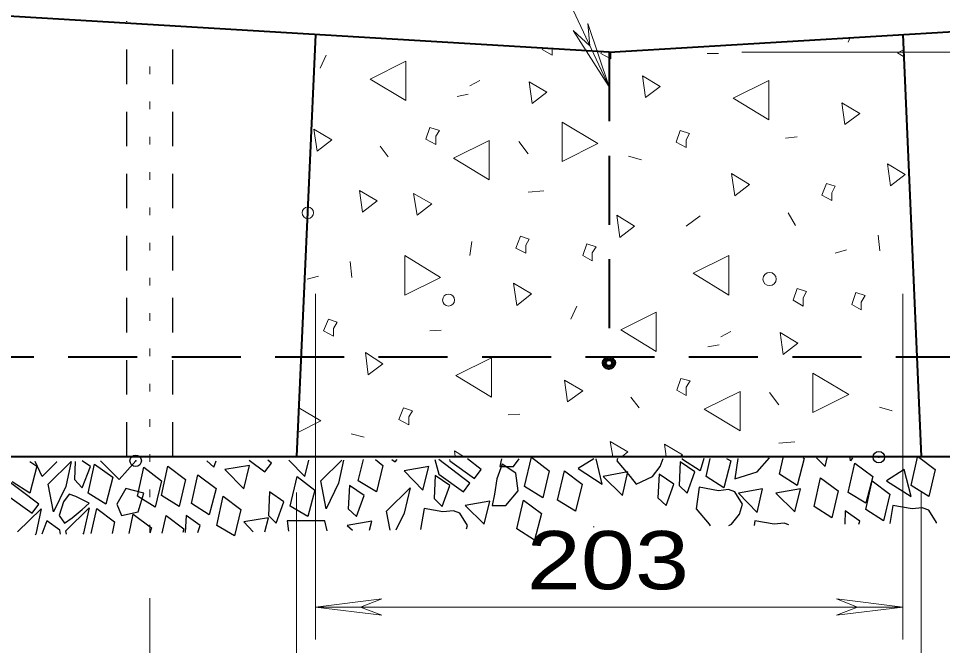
# Model space of a CAD drawing. Extents: x 312583 to 312854, y 144419 to 144597.
# Drawn here: x 312703.67 to 312715.73, y 144449.15 to 144457.33 of the extents above; entities that cross this region are included whole.
import ezdxf

# ---------------------------------------------------------------- set-up
doc = ezdxf.new("R2010")
doc.units = 0
doc.header["$LTSCALE"] = 0.3
doc.header["$PDMODE"] = 32
doc.header["$PDSIZE"] = 0.15
for name, pattern in [('DOTTED', [1.5, 0.3, -1.2]), ('MEDIUM_DASHED', [4.5, 3, -1.5]), ('SHORT_DASHED', [2.7, 1.5, -1.2])]:
    doc.linetypes.add(name, pattern=pattern)
doc.layers.add('1', color=7, linetype='Continuous', lineweight=25)
doc.layers.add('2', color=7, linetype='Continuous', lineweight=13)

msp = doc.modelspace()

# ---------------------------------------------------------------- linework, layer by layer
at = {"layer": '1', "lineweight": 40}
for p, q in [((312711.376, 144456.89), (312703.464, 144457.3654)), ((312711.376, 144456.89), (312719.2804, 144457.3654)), ((312707.5427, 144457.12), (312707.2974, 144451.6154)), ((312715.2094, 144457.12), (312715.447, 144451.6154)), ((312697.001, 144451.6154), (312725.751, 144451.6154))]:
    msp.add_line(p, q, dxfattribs=at)
at = {"layer": '1', "linetype": 'SHORT_DASHED'}
for p, q in [((312705.0817, 144451.6154), (312705.0817, 144457.2964)), ((312705.6797, 144451.6154), (312705.6797, 144457.258))]:
    msp.add_line(p, q, dxfattribs=at)
at = {"layer": '1', "linetype": 'MEDIUM_DASHED', "lineweight": 40}
for p, q in [((312711.376, 144456.89), (312711.376, 144452.9187)), ((312698.9177, 144452.9187), (312723.8344, 144452.9187))]:
    msp.add_line(p, q, dxfattribs=at)
at = {"layer": '1'}
for p, q in [((312708.1024, 144451.301), (312708.1714, 144451.577)), ((312709.099, 144451.577), (312709.1527, 144451.3854)), ((312709.2907, 144451.577), (312709.2984, 144451.5617)), ((312711.1767, 144451.5847), (312710.9697, 144451.462)), ((312712.3344, 144451.577), (312712.3344, 144451.5924)), ((312712.641, 144451.3547), (312712.6947, 144451.5924)), ((312713.5994, 144451.3854), (312713.6454, 144451.6)), ((312715.3167, 144451.2397), (312715.401, 144451.6077)), ((312703.9777, 144451.3547), (312703.8857, 144451.554)), ((312707.6117, 144451.301), (312707.8877, 144451.5694)), ((312708.5164, 144450.657), (312708.4704, 144450.9024)), ((312714.458, 144450.91), (312714.4504, 144450.7337)), ((312704.039, 144450.7797), (312703.97, 144450.6034)), ((312705.856, 144450.8487), (312705.8407, 144450.6264)), ((312706.6074, 144450.7644), (312706.73, 144450.634)), ((312712.6794, 144450.7337), (312712.6947, 144450.7107)), ((312704.292, 144450.6034), (312704.2844, 144450.6494)), ((312707.9567, 144450.7184), (312708.0257, 144450.657)), ((312711.1767, 144450.6954), (312711.1767, 144450.703))]:
    msp.add_line(p, q, dxfattribs=at)
for points in [[(312708.3247, 144451.577), (312708.4244, 144451.5004), (312708.34, 144451.1554), (312708.1024, 144451.301)], [(312708.5394, 144451.577), (312708.5854, 144451.5464), (312708.6084, 144451.577)], [(312709.1527, 144451.3854), (312709.4747, 144451.1554), (312709.559, 144451.2704), (312709.1527, 144451.577)], [(312709.2984, 144451.5617), (312709.6204, 144451.3317), (312709.7047, 144451.4467), (312709.5284, 144451.5847)], [(312709.973, 144451.5847), (312709.95, 144451.485), (312710.1264, 144451.485), (312710.203, 144451.5847)], [(312710.9697, 144451.462), (312711.284, 144451.255), (312711.2074, 144451.5847)], [(312711.4834, 144451.5924), (312711.4757, 144451.5617), (312711.652, 144451.3547)], [(312711.652, 144451.3547), (312711.7287, 144451.255), (312711.9434, 144451.3547), (312712.043, 144451.485), (312712.0814, 144451.5924)], [(312712.6104, 144451.5924), (312712.5644, 144451.4314), (312712.3344, 144451.577)], [(312712.9094, 144451.5924), (312712.963, 144451.5617), (312712.871, 144451.209), (312712.641, 144451.3547)], [(312713.055, 144451.5924), (312713.0167, 144451.324), (312713.308, 144451.416), (312713.469, 144451.6)], [(312713.906, 144451.6), (312713.9214, 144451.5924), (312713.8294, 144451.2397), (312713.5994, 144451.3854)], [(312714.0824, 144451.6), (312714.1974, 144451.485), (312714.2204, 144451.6)], [(312714.55, 144451.6), (312714.527, 144451.5617), (312714.5194, 144451.6)], [(312715.4164, 144451.6077), (312715.631, 144451.4467), (312715.5467, 144451.094), (312715.3167, 144451.2397)], [(312703.8167, 144451.554), (312703.9087, 144451.4927), (312703.8167, 144451.14), (312703.5867, 144451.2857)], [(312704.1617, 144451.554), (312704.1694, 144451.5464), (312703.9777, 144451.3547)], [(312704.407, 144451.554), (312704.3994, 144451.3164), (312704.499, 144451.209), (312704.6064, 144451.485), (312704.499, 144451.5617)], [(312704.7367, 144451.5617), (312704.982, 144451.3164), (312705.1967, 144451.5617)], [(312706.1244, 144451.5617), (312706.2164, 144451.4774), (312706.247, 144451.5617)], [(312706.6764, 144451.5694), (312706.8834, 144451.416), (312706.9677, 144451.531), (312706.9217, 144451.5694)], [(312707.1977, 144451.5694), (312707.4047, 144451.3547), (312707.4584, 144451.5694)], [(312707.9107, 144451.5694), (312707.8417, 144451.2704), (312707.6807, 144450.933), (312707.6117, 144451.301)], [(312712.94, 144450.7184), (312712.9707, 144450.7337), (312713.078, 144450.864), (312713.1164, 144450.9944), (312713.0167, 144451.1554), (312712.9324, 144451.186), (312712.802, 144451.1707), (312712.549, 144451.2167), (312712.5107, 144450.933), (312712.6794, 144450.7337)], [(312708.4704, 144450.9024), (312708.777, 144451.209), (312708.7004, 144450.8794), (312708.593, 144450.657)], [(312715.6464, 144450.749), (312715.6464, 144450.7567), (312715.5467, 144450.9177), (312715.4624, 144450.9484), (312715.332, 144450.933), (312715.079, 144450.979), (312715.0407, 144450.7414)], [(312703.6557, 144450.634), (312703.9624, 144450.933), (312703.8934, 144450.6034), (312703.8857, 144450.5957)], [(312704.2844, 144450.6494), (312704.591, 144450.9484), (312704.5144, 144450.6187), (312704.5067, 144450.6034)], [(312704.614, 144450.611), (312704.6907, 144450.9407), (312704.9207, 144450.7644), (312704.89, 144450.611)], [(312705.1124, 144450.611), (312705.166, 144450.864), (312705.4037, 144450.6877), (312705.3807, 144450.6187)], [(312709.513, 144450.6724), (312709.5284, 144450.7184), (312709.4287, 144450.8794), (312709.3444, 144450.91), (312709.2064, 144450.8947), (312708.961, 144450.9407), (312708.915, 144450.6647)], [(312714.6344, 144450.7337), (312714.6497, 144450.772), (312714.458, 144450.91)], [(312704.2154, 144450.6034), (312704.2077, 144450.657), (312704.039, 144450.7797)], [(312705.5417, 144450.6187), (312705.5954, 144450.8487), (312705.8254, 144450.6724), (312705.81, 144450.6264)], [(312706.0094, 144450.6264), (312706.04, 144450.7184), (312705.856, 144450.8487)], [(312706.8834, 144450.634), (312706.9294, 144450.818), (312706.6074, 144450.7644)], [(312707.696, 144450.6494), (312707.6654, 144450.7797), (312707.1747, 144450.7797), (312707.19, 144450.6417)], [(312708.248, 144450.657), (312708.2787, 144450.772), (312707.9567, 144450.7184)], [(312713.722, 144450.726), (312713.6607, 144450.749), (312713.5304, 144450.7337), (312713.2774, 144450.7797), (312713.2697, 144450.7184)]]:
    msp.add_lwpolyline(points, dxfattribs=at)
for points in [[(312710.272, 144451.2244), (312710.364, 144451.6077), (312710.594, 144451.4314), (312710.5097, 144451.0787)], [(312704.0544, 144451.255), (312704.3534, 144451.554), (312704.2844, 144451.2244), (312704.1234, 144450.8947)], [(312704.5757, 144451.14), (312704.66, 144451.5157), (312704.8977, 144451.347), (312704.8057, 144450.9944)], [(312705.2197, 144451.1017), (312705.304, 144451.4774), (312705.534, 144451.301), (312705.4497, 144450.956)], [(312705.534, 144451.1094), (312705.6184, 144451.4927), (312705.8484, 144451.3164), (312705.764, 144450.9637)], [(312706.362, 144451.4467), (312706.6074, 144451.1937), (312706.684, 144451.5004)], [(312708.7004, 144451.4314), (312708.9457, 144451.1784), (312709.0224, 144451.485)], [(312709.9807, 144451.5157), (312709.9117, 144451.324), (312709.881, 144451.1247), (312709.8504, 144450.979), (312710.0267, 144450.979), (312710.1877, 144451.1707), (312710.157, 144451.4007)], [(312712.3037, 144451.5464), (312712.2884, 144451.2397), (312712.3957, 144451.14), (312712.4954, 144451.416)], [(312714.4964, 144451.1477), (312714.5807, 144451.531), (312714.8184, 144451.3547), (312714.7264, 144451.0097)], [(312703.5254, 144451.1094), (312703.8474, 144450.8794), (312703.9317, 144450.9944), (312703.4564, 144451.3547)], [(312705.925, 144451.002), (312706.0094, 144451.3777), (312706.247, 144451.2014), (312706.155, 144450.8564)], [(312707.213, 144450.9714), (312707.305, 144451.3547), (312707.535, 144451.1784), (312707.443, 144450.8334)], [(312709.1067, 144451.37), (312709.0914, 144451.071), (312709.1987, 144450.9637), (312709.2984, 144451.2397)], [(312710.7014, 144451.048), (312710.7934, 144451.4314), (312711.0234, 144451.255), (312710.939, 144450.9024)], [(312711.2994, 144451.3547), (312711.5524, 144451.1094), (312711.6214, 144451.416)], [(312712.0277, 144451.3854), (312712.0124, 144451.0787), (312712.1197, 144450.979), (312712.2194, 144451.255)], [(312714.0517, 144450.9637), (312714.136, 144451.3394), (312714.366, 144451.1707), (312714.2817, 144450.818)], [(312714.9947, 144451.301), (312715.3167, 144451.094), (312715.2247, 144451.4467)], [(312707.9874, 144451.2397), (312707.972, 144450.933), (312708.0794, 144450.8334), (312708.179, 144451.1094)], [(312714.7264, 144450.9254), (312714.8107, 144451.301), (312715.0407, 144451.1247), (312714.9564, 144450.7797)], [(312704.4147, 144451.094), (312704.3304, 144451.1247), (312704.2537, 144451.025), (312704.2, 144450.8487), (312704.269, 144450.749), (312704.3687, 144450.818), (312704.499, 144450.9254), (312704.591, 144451.0097)], [(312705.0664, 144451.2014), (312704.9514, 144450.9944), (312705.0127, 144450.8487), (312705.2274, 144450.8947), (312705.304, 144451.14)], [(312706.2547, 144450.7184), (312706.339, 144451.1017), (312706.569, 144450.9254), (312706.4847, 144450.5804)], [(312706.9447, 144451.1554), (312706.9294, 144450.8487), (312707.029, 144450.749), (312707.1287, 144451.025)], [(312713.0627, 144451.14), (312713.308, 144450.887), (312713.377, 144451.1937)], [(312713.5534, 144451.14), (312713.7987, 144450.8947), (312713.8754, 144451.1937)], [(312709.4977, 144450.979), (312709.743, 144450.7337), (312709.8197, 144451.0327)], [(312710.1724, 144450.6724), (312710.2567, 144451.048), (312710.4944, 144450.8717), (312710.4024, 144450.5267)]]:
    msp.add_lwpolyline(points, close=True, dxfattribs=at)
at = {"layer": '1', "lineweight": 40}
for radius in [0.0799, 0.0559, 0.0391]:
    msp.add_circle((312711.3732, 144452.8369), radius, dxfattribs=at)
at = {"layer": '1'}
for p in [(312705.1967, 144451.5617), (312714.895, 144451.6077)]:
    msp.add_point(p, dxfattribs=at)
at = {"layer": '2'}
for p, q in [((312711.1, 144457.2657), (312711.123, 144456.9744)), ((312711.376, 144456.4377), (312711.1, 144457.2657)), ((312710.9084, 144457.1737), (312711.123, 144456.9744)), ((312711.376, 144456.4377), (312710.9084, 144457.1737)), ((312714.5194, 144457.0817), (312714.4964, 144457.0204)), ((312713.1087, 144456.89), (312728.9864, 144456.89)), ((312707.6807, 144456.8517), (312707.604, 144456.683)), ((312712.6564, 144456.8747), (312712.802, 144456.8747)), ((312709.559, 144456.453), (312709.6894, 144456.522)), ((312709.3904, 144456.315), (312709.536, 144456.3457)), ((312710.1954, 144455.7247), (312710.318, 144455.5637)), ((312713.676, 144455.7707), (312713.8294, 144455.786)), ((312708.386, 144455.6634), (312708.4934, 144455.5254)), ((312711.629, 144455.533), (312711.7977, 144455.487)), ((312710.318, 144455.0654), (312710.525, 144455.0807)), ((312712.5644, 144454.7587), (312712.3804, 144454.6207)), ((312713.7144, 144454.797), (312713.8064, 144454.6284)), ((312714.8874, 144454.5057), (312714.9104, 144454.2987)), ((312709.559, 144454.2374), (312709.582, 144454.4214)), ((312714.3277, 144454.268), (312714.4734, 144454.314)), ((312707.995, 144454.1607), (312708.018, 144453.9537)), ((312707.4354, 144453.9307), (312707.581, 144453.969)), ((312707.5427, 144453.739), (312707.5427, 144449.231)), ((312715.2094, 144453.739), (312715.2094, 144449.231)), ((312710.9544, 144453.578), (312710.8777, 144453.4094)), ((312709.0377, 144453.256), (312709.1834, 144453.2637)), ((312712.8327, 144453.1794), (312712.963, 144453.2484)), ((312712.664, 144453.049), (312712.8097, 144453.072)), ((312713.469, 144452.451), (312713.5917, 144452.29)), ((312711.6597, 144452.3897), (312711.767, 144452.2517)), ((312714.9027, 144452.2594), (312715.0714, 144452.2134)), ((312710.0574, 144452.1597), (312710.2107, 144452.1674)), ((312708.0104, 144451.9144), (312708.179, 144451.8684)), ((312713.5917, 144451.7917), (312713.7987, 144451.807)), ((312707.2974, 144451.1477), (312707.2974, 144447.7207)), ((312715.447, 144451.1477), (312715.447, 144447.7207)), ((312705.3807, 144449.7677), (312705.3807, 144447.7207)), ((312707.5427, 144449.6527), (312708.409, 144449.76)), ((312707.5427, 144449.6527), (312715.2094, 144449.6527)), ((312707.5427, 144449.6527), (312708.409, 144449.5454)), ((312708.409, 144449.76), (312708.133, 144449.6527)), ((312708.409, 144449.5454), (312708.133, 144449.6527)), ((312714.343, 144449.76), (312714.619, 144449.6527)), ((312715.2094, 144449.6527), (312714.343, 144449.76)), ((312714.343, 144449.5454), (312714.619, 144449.6527)), ((312715.2094, 144449.6527), (312714.343, 144449.5454))]:
    msp.add_line(p, q, dxfattribs=at)
at = {"layer": '2', "linetype": 'DOTTED'}
msp.add_line((312705.3807, 144456.706), (312705.3807, 144450.496), dxfattribs=at)
at = {"layer": '2'}
for points in [[(312709.697, 144461.6664), (312708.9227, 144461.6664), (312711.376, 144456.4377)], [(312710.5097, 144456.9437), (312710.502, 144456.9284), (312710.6324, 144456.8517), (312710.6324, 144456.936)], [(312711.2764, 144456.89), (312711.2687, 144456.8747), (312711.399, 144456.8057), (312711.399, 144456.89)], [(312715.217, 144456.9207), (312715.1404, 144456.8824), (312715.217, 144456.8364)], [(312707.3127, 144451.9297), (312707.6117, 144452.083), (312707.328, 144452.2517)], [(312711.5447, 144451.6154), (312711.6214, 144451.6767), (312711.3914, 144451.8147), (312711.422, 144451.6154)], [(312712.3037, 144451.6154), (312712.3344, 144451.6384), (312712.0967, 144451.7764), (312712.1197, 144451.6154)], [(312709.4747, 144451.6154), (312709.3597, 144451.692), (312709.3674, 144451.6154)]]:
    msp.add_lwpolyline(points, dxfattribs=at)
for points in [[(312708.7234, 144456.2614), (312708.7234, 144456.775), (312708.2557, 144456.5374)], [(312711.8514, 144456.2997), (312712.043, 144456.4454), (312711.813, 144456.5834)], [(312713.4614, 144456.0084), (312713.4614, 144456.522), (312712.9937, 144456.292)], [(312710.3717, 144456.223), (312710.5634, 144456.3687), (312710.3334, 144456.5067)], [(312714.4504, 144455.947), (312714.6497, 144456.0927), (312714.412, 144456.2307)], [(312710.7627, 144455.9777), (312710.7627, 144455.464), (312711.2304, 144455.7017)], [(312707.5657, 144455.602), (312707.7574, 144455.7477), (312707.5197, 144455.8857)], [(312709.1144, 144455.7937), (312709.1604, 144455.8704), (312709.0377, 144455.9087), (312708.984, 144455.7554), (312709.1144, 144455.6864)], [(312712.3804, 144455.7477), (312712.4264, 144455.832), (312712.3037, 144455.8704), (312712.25, 144455.717), (312712.3804, 144455.648)], [(312709.812, 144455.2264), (312709.812, 144455.74), (312709.3444, 144455.51)], [(312715.0484, 144455.1497), (312715.24, 144455.2954), (312715.01, 144455.4334)], [(312713.0167, 144455.0194), (312713.2084, 144455.165), (312712.9707, 144455.3107)], [(312708.156, 144454.8047), (312708.3477, 144454.9504), (312708.1177, 144455.0884)], [(312714.2817, 144455.0577), (312714.3277, 144455.142), (312714.2127, 144455.1804), (312714.1514, 144455.027), (312714.2817, 144454.958)], [(312708.869, 144454.7664), (312709.0607, 144454.912), (312708.823, 144455.05)], [(312711.514, 144454.475), (312711.7057, 144454.6207), (312711.4757, 144454.7664)], [(312710.2874, 144454.3754), (312710.3334, 144454.452), (312710.2184, 144454.4904), (312710.157, 144454.337), (312710.2874, 144454.268)], [(312711.1537, 144454.2757), (312711.2074, 144454.3524), (312711.0847, 144454.3907), (312711.031, 144454.2374), (312711.1537, 144454.1684)], [(312708.708, 144454.2374), (312708.708, 144453.7237), (312709.1757, 144453.9537)], [(312712.94, 144453.7237), (312712.94, 144454.2374), (312712.4724, 144454.0074)], [(312710.1724, 144453.5857), (312710.364, 144453.739), (312710.1264, 144453.877)], [(312713.906, 144453.6854), (312713.952, 144453.7697), (312713.8294, 144453.808), (312713.7757, 144453.6547), (312713.906, 144453.578)], [(312714.665, 144453.6317), (312714.7187, 144453.716), (312714.596, 144453.7544), (312714.5424, 144453.601), (312714.665, 144453.532)], [(312707.7804, 144453.2867), (312707.8264, 144453.371), (312707.7114, 144453.4094), (312707.65, 144453.256), (312707.7804, 144453.187)], [(312711.9894, 144452.9877), (312711.9894, 144453.5014), (312711.5294, 144453.2714)], [(312713.6454, 144452.9494), (312713.837, 144453.095), (312713.607, 144453.233)], [(312708.2327, 144452.681), (312708.4244, 144452.8267), (312708.1944, 144452.9724)], [(312709.8427, 144452.3897), (312709.8427, 144452.9034), (312709.375, 144452.6734)], [(312714.0364, 144452.704), (312714.0364, 144452.1904), (312714.504, 144452.428)], [(312710.8317, 144452.3284), (312711.031, 144452.474), (312710.7934, 144452.612)], [(312712.3804, 144452.52), (312712.434, 144452.6044), (312712.3114, 144452.635), (312712.2577, 144452.4817), (312712.3804, 144452.4127)], [(312713.0857, 144451.9527), (312713.0857, 144452.4664), (312712.618, 144452.2364)], [(312708.7617, 144452.1367), (312708.8077, 144452.2134), (312708.6927, 144452.2517), (312708.6314, 144452.0984), (312708.7617, 144452.0294)]]:
    msp.add_lwpolyline(points, close=True, dxfattribs=at)
for centre, radius in [((312713.4703, 144453.9322), 0.0865), ((312709.2801, 144453.6582), 0.0784)]:
    msp.add_circle(centre, radius, dxfattribs=at)
msp.add_point((312707.443, 144454.797), dxfattribs=at)

# ---------------------------------------------------------------- texts
at = {"layer": '2', "width": 1.25}
msp.add_text('203 ', height=0.76, dxfattribs=at).set_placement((312710.2997, 144449.8852))

doc.saveas('drawing.dxf')
